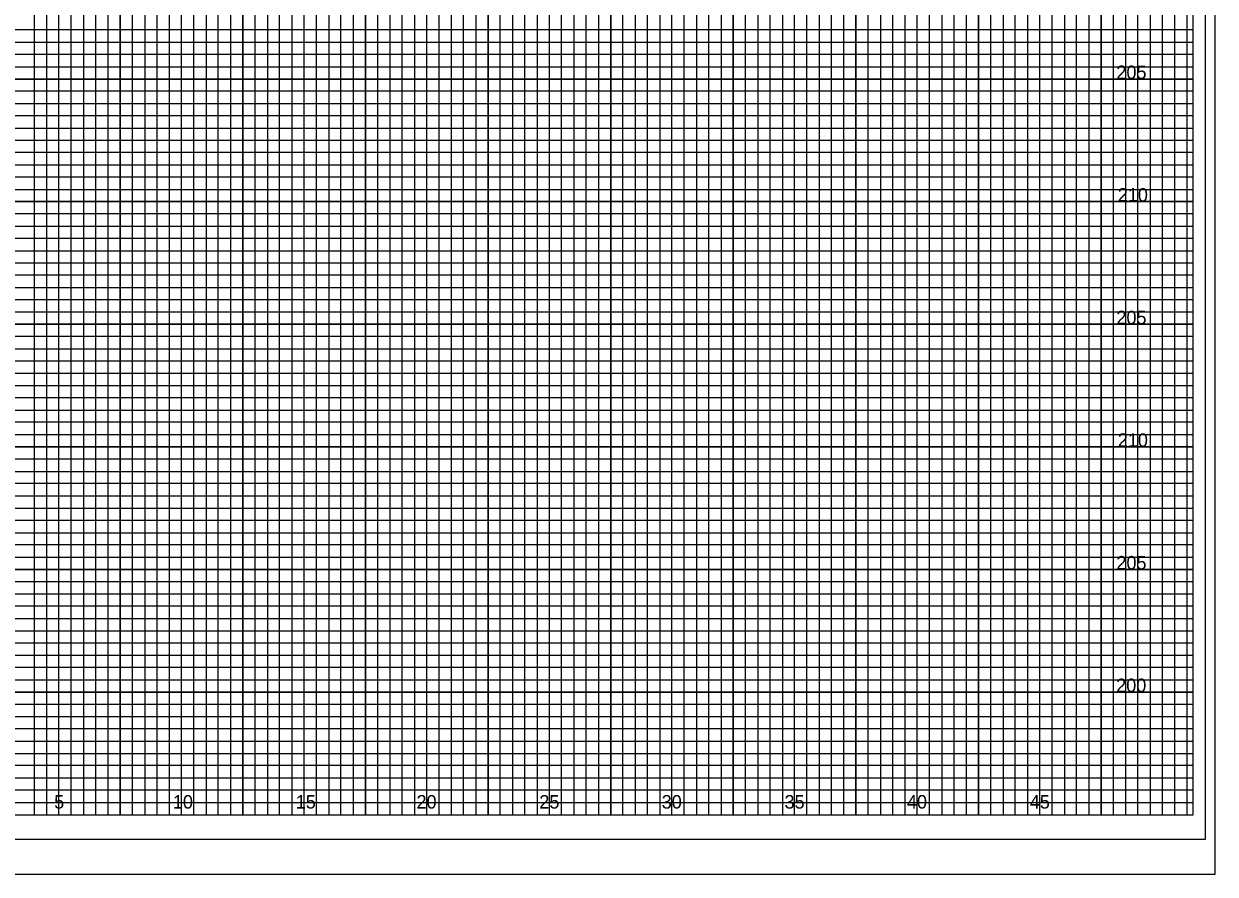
# Model space of a CAD drawing. Extents: x -4 to 103, y -2 to 492.
# Drawn here: x 54.82 to 103.4, y -2.42 to 32.25 of the extents above; entities that cross this region are included whole.
import ezdxf

# ---------------------------------------------------------------- set-up
doc = ezdxf.new("R2010")
doc.units = 0
for name, color, linetype in [('Old_Level_10', 7, 'Continuous'), ('Old_Level_16', 7, 'Continuous'), ('Old_Level_3', 7, 'Continuous'), ('Old_Level_5', 7, 'Continuous'), ('Old_Level_8', 7, 'Continuous'), ('Prop Dimension', 7, 'Continuous'), ('Prop XS Finish Grade Earthwork', 7, 'Continuous'), ('Prop XS SE Text', 7, 'Continuous'), ('Prop XSC Text', 7, 'Continuous')]:
    doc.layers.add(name, color=color, linetype=linetype)

msp = doc.modelspace()

# ---------------------------------------------------------------- linework, layer by layer
at = {"layer": 'Old_Level_10'}
for p, q in [((56.25, 0), (56.25, 65)), ((58.75, 0), (58.75, 65)), ((61.25, 0), (61.25, 65)), ((63.75, 0), (63.75, 65)), ((66.25, 0), (66.25, 65)), ((68.75, 0), (68.75, 65)), ((71.25, 0), (71.25, 65)), ((73.75, 0), (73.75, 65)), ((91.25, 0), (91.25, 63.425)), ((93.75, 0), (93.75, 63.425)), ((96.25, 0), (96.25, 63.425)), ((98.75, 0), (98.75, 63.425)), ((101.25, 0), (101.25, 63.425)), ((76.25, 0), (76.25, 62)), ((78.75, 0), (78.75, 62)), ((81.25, 0), (81.25, 62)), ((83.75, 0), (83.75, 62)), ((86.25, 0), (86.25, 62)), ((88.75, 0), (88.75, 62)), ((0, 30), (102.5, 30)), ((0, 27.5), (102.5, 27.5)), ((0, 25), (102.5, 25)), ((0, 22.5), (102.5, 22.5)), ((0, 20), (102.5, 20)), ((0, 17.5), (102.5, 17.5)), ((0, 15), (102.5, 15)), ((0, 12.5), (102.5, 12.5)), ((0, 10), (102.5, 10)), ((0, 7.5), (102.5, 7.5)), ((0, 5), (102.5, 5)), ((0, 2.5), (102.5, 2.5))]:
    msp.add_line(p, q, dxfattribs=at)
at = {"layer": 'Old_Level_3'}
msp.add_line((-3.5, -2.425), (103.4, -2.425), dxfattribs=at)
at = {"layer": 'Old_Level_5'}
msp.add_lwpolyline([(103.4, 67.4), (-3.5, 67.4), (-3.5, -2.425), (103.4, -2.425)], close=True, dxfattribs=at)
at = {"layer": 'Old_Level_8'}
for points in [[(56.25, 0), (56.25, 65)], [(58.75, 65), (58.75, 0), (61.25, 0), (61.25, 65)], [(63.75, 65), (63.75, 0), (66.25, 0), (66.25, 65)], [(68.75, 65), (68.75, 0), (71.25, 0), (71.25, 65)], [(73.75, 65), (73.75, 0), (76.25, 0), (76.25, 62)], [(88.75, 62), (88.75, 0), (91.25, 0), (91.25, 63.425)], [(93.75, 63.425), (93.75, 0), (96.25, 0), (96.25, 63.425)], [(98.75, 63.425), (98.75, 0), (101.25, 0), (101.25, 63.425)], [(78.75, 62), (78.75, 0), (81.25, 0), (81.25, 62)], [(83.75, 62), (83.75, 0), (86.25, 0), (86.25, 62)], [(0, 27.5), (102.5, 27.5), (102.5, 30), (0, 30)], [(0, 22.5), (102.5, 22.5), (102.5, 25), (0, 25)], [(0, 17.5), (102.5, 17.5), (102.5, 20), (0, 20)], [(0, 12.5), (102.5, 12.5), (102.5, 15), (0, 15)], [(0, 7.5), (102.5, 7.5), (102.5, 10), (0, 10)], [(0, 2.5), (102.5, 2.5), (102.5, 5), (0, 5)]]:
    msp.add_lwpolyline(points, dxfattribs=at)
at = {"layer": 'Prop Dimension'}
for points in [[(54.75, 0), (55.25, 0), (55.25, 65)], [(55.75, 65), (55.75, 0), (56.75, 0), (56.75, 65)], [(57.25, 65), (57.25, 0), (57.75, 0), (57.75, 65)], [(58.25, 65), (58.25, 0), (59.25, 0), (59.25, 65)], [(59.75, 65), (59.75, 0), (60.25, 0), (60.25, 65)], [(60.75, 65), (60.75, 0), (61.75, 0), (61.75, 65)], [(62.25, 65), (62.25, 0), (62.75, 0), (62.75, 65)], [(63.25, 65), (63.25, 0), (64.25, 0), (64.25, 65)], [(64.75, 65), (64.75, 0), (65.25, 0), (65.25, 65)], [(65.75, 65), (65.75, 0), (66.75, 0), (66.75, 65)], [(67.25, 65), (67.25, 0), (67.75, 0), (67.75, 65)], [(68.25, 65), (68.25, 0), (69.25, 0), (69.25, 65)], [(69.75, 65), (69.75, 0), (70.25, 0), (70.25, 65)], [(70.75, 65), (70.75, 0), (71.75, 0), (71.75, 65)], [(72.25, 65), (72.25, 0), (72.75, 0), (72.75, 65)], [(73.25, 65), (73.25, 0), (74.25, 0), (74.25, 62)], [(89.75, 62), (89.75, 0), (90.25, 0), (90.25, 63.425)], [(90.75, 63.425), (90.75, 0), (91.75, 0), (91.75, 63.425)], [(92.25, 63.425), (92.25, 0), (92.75, 0), (92.75, 63.425)], [(93.25, 63.425), (93.25, 0), (94.25, 0), (94.25, 63.425)], [(94.75, 63.425), (94.75, 0), (95.25, 0), (95.25, 63.425)], [(95.75, 63.425), (95.75, 0), (96.75, 0), (96.75, 63.425)], [(97.25, 63.425), (97.25, 0), (97.75, 0), (97.75, 63.425)], [(98.25, 63.425), (98.25, 0), (99.25, 0), (99.25, 63.425)], [(99.75, 63.425), (99.75, 0), (100.25, 0), (100.25, 63.425)], [(100.25, 63.425), (100.75, 63.425), (100.75, 0), (101.75, 0), (101.75, 63.425), (102.25, 63.425), (102.25, 0)], [(74.75, 62), (74.75, 0), (75.25, 0), (75.25, 62)], [(75.75, 62), (75.75, 0), (76.75, 0), (76.75, 62)], [(77.25, 62), (77.25, 0), (77.75, 0), (77.75, 62)], [(78.25, 62), (78.25, 0), (79.25, 0), (79.25, 62)], [(79.75, 62), (79.75, 0), (80.25, 0), (80.25, 62)], [(80.75, 62), (80.75, 0), (81.75, 0), (81.75, 62)], [(82.25, 62), (82.25, 0), (82.75, 0), (82.75, 62)], [(83.25, 62), (83.25, 0), (84.25, 0), (84.25, 62)], [(84.75, 62), (84.75, 0), (85.25, 0), (85.25, 62)], [(85.75, 62), (85.75, 0), (86.75, 0), (86.75, 62)], [(87.25, 62), (87.25, 0), (87.75, 0), (87.75, 62)], [(88.25, 62), (88.25, 0), (89.25, 0), (89.25, 62)], [(0, 31.5), (102.5, 31.5), (102.5, 32), (0, 32)], [(0, 30.5), (102.5, 30.5), (102.5, 31), (0, 31)], [(0, 29), (102.5, 29), (102.5, 29.5), (0, 29.5)], [(0, 28), (102.5, 28), (102.5, 28.5), (0, 28.5)], [(0, 26.5), (102.5, 26.5), (102.5, 27), (0, 27)], [(0, 25.5), (102.5, 25.5), (102.5, 26), (0, 26)], [(0, 24), (102.5, 24), (102.5, 24.5), (0, 24.5)], [(0, 23), (102.5, 23), (102.5, 23.5), (0, 23.5)], [(0, 21.5), (102.5, 21.5), (102.5, 22), (0, 22)], [(0, 20.5), (102.5, 20.5), (102.5, 21), (0, 21)], [(0, 19), (102.5, 19), (102.5, 19.5), (0, 19.5)], [(0, 18), (102.5, 18), (102.5, 18.5), (0, 18.5)], [(0, 16.5), (102.5, 16.5), (102.5, 17), (0, 17)], [(0, 15.5), (102.5, 15.5), (102.5, 16), (0, 16)], [(0, 14), (102.5, 14), (102.5, 14.5), (0, 14.5)], [(0, 13), (102.5, 13), (102.5, 13.5), (0, 13.5)], [(0, 11.5), (102.5, 11.5), (102.5, 12), (0, 12)], [(0, 10.5), (102.5, 10.5), (102.5, 11), (0, 11)], [(0, 9), (102.5, 9), (102.5, 9.5), (0, 9.5)], [(0, 8), (102.5, 8), (102.5, 8.5), (0, 8.5)], [(0, 6.5), (102.5, 6.5), (102.5, 7), (0, 7)], [(0, 5.5), (102.5, 5.5), (102.5, 6), (0, 6)], [(0, 4), (102.5, 4), (102.5, 4.5), (0, 4.5)], [(0, 3), (102.5, 3), (102.5, 3.5), (0, 3.5)], [(0, 1.5), (102.5, 1.5), (102.5, 2), (0, 2)], [(0, 0.5), (102.5, 0.5), (102.5, 1), (0, 1)]]:
    msp.add_lwpolyline(points, dxfattribs=at)
at = {"layer": 'Prop XS SE Text'}
msp.add_lwpolyline([(103, 66), (-2.8, 66), (-2.8, -1), (103, -1)], close=True, dxfattribs=at)
at = {"layer": 'Prop XSC Text'}
msp.add_lwpolyline([(102.5, 65), (0, 65), (0, 0), (102.5, 0)], close=True, dxfattribs=at)

# ---------------------------------------------------------------- texts
at = {"layer": 'Old_Level_16'}
for s, p in [('5', (56.0574, 0.25)), ('10', (60.8971, 0.25)), ('15', (65.9057, 0.25)), ('20', (70.8312, 0.25)), ('25', (75.8399, 0.25)), ('30', (80.8312, 0.25)), ('35', (85.8399, 0.25)), ('40', (90.8313, 0.25)), ('45', (95.8399, 0.25))]:
    msp.add_text(s, height=0.55, dxfattribs=at).set_placement(p)
at = {"layer": 'Prop XS Finish Grade Earthwork'}
for s, p in [('205', (99.3724, 30)), ('210', (99.4296, 25)), ('205', (99.3724, 20)), ('210', (99.4296, 15)), ('205', (99.3724, 10)), ('200', (99.3638, 5))]:
    msp.add_text(s, height=0.55, dxfattribs=at).set_placement(p)

doc.saveas('drawing.dxf')
